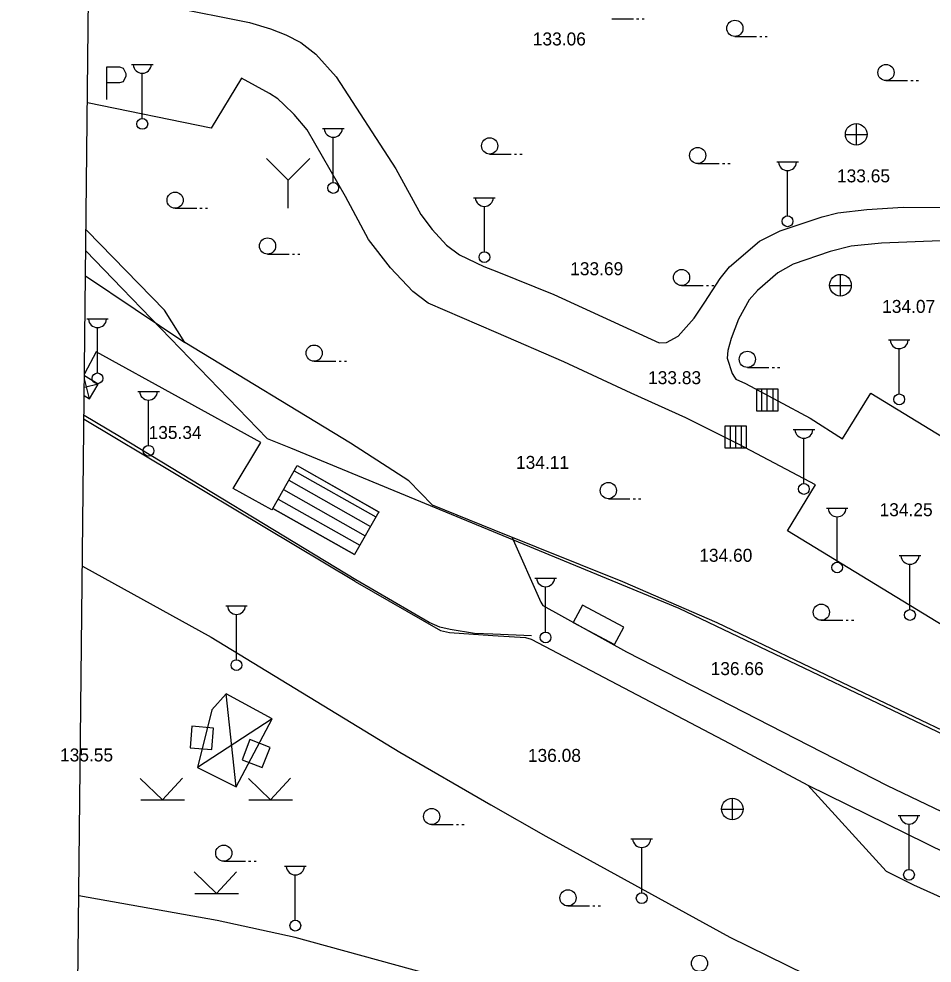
# Model space of a CAD drawing. Extents: x 419101 to 420177, y 4451541 to 4452254.
# Drawn here: x 419101.3 to 419185.8, y 4452064.5 to 4452151.9 of the extents above; entities that cross this region are included whole.
import ezdxf

# ---------------------------------------------------------------- set-up
doc = ezdxf.new("R2010")
doc.units = 0
for name, color, linetype in [('0_ÖNERİ_LEJAND', 7, 'Continuous'), ('2_KADASTRO', 7, 'Continuous'), ('3_HALİHAZIR', 7, 'Continuous')]:
    doc.layers.add(name, color=color, linetype=linetype)

msp = doc.modelspace()

# ---------------------------------------------------------------- linework, layer by layer
at = {"layer": '0_ÖNERİ_LEJAND'}
msp.add_lwpolyline([(419108.722, 4452245.778), (420173.096, 4452234.536), (420165.768, 4451540.511), (419101.295, 4451551.753)], close=True, dxfattribs=at)
at = {"layer": '2_KADASTRO'}
msp.add_lwpolyline([(419107.487, 4452130.446), (419110.859, 4452126.96), (419124.272, 4452113.097), (419126.42, 4452112.21), (419162.35, 4452097.37), (419191.66, 4452083.39), (419209.499, 4452074.263), (419232.354, 4452055.784), (419235.998, 4452053.197), (419252.71, 4452048.61), (419263.65, 4452045.93), (419298.16, 4452038.82), (419313.21, 4452052.63), (419335.67, 4452052.54), (419357.03, 4452053.91), (419363.44, 4452040.24), (419369.82, 4452028.71), (419391.34, 4452027.13), (419408.91, 4452026.12), (419429.01, 4452025.67), (419447.58, 4452025.47), (419467.18, 4452025.82), (419487.11, 4452026.7), (419516.66, 4452028.96)], dxfattribs=at)
at = {"layer": '3_HALİHAZIR'}
for p, q in [((419156.13, 4452151.913), (419158.13, 4452151.913)), ((419158.43, 4452151.913), (419158.63, 4452151.913)), ((419158.93, 4452151.913), (419159.13, 4452151.913)), ((419167.52, 4452150.289), (419169.52, 4452150.289)), ((419169.82, 4452150.289), (419170.02, 4452150.289)), ((419170.32, 4452150.289), (419170.52, 4452150.289)), ((419111.708, 4452147.695), (419113.708, 4452147.695)), ((419112.708, 4452142.695), (419112.708, 4452146.888)), ((419181.496, 4452146.199), (419183.496, 4452146.199)), ((419183.796, 4452146.199), (419183.996, 4452146.199)), ((419184.296, 4452146.199), (419184.496, 4452146.199)), ((419129.372, 4452141.768), (419131.372, 4452141.768)), ((419178.76, 4452140.22), (419178.76, 4452142.22)), ((419130.372, 4452136.768), (419130.372, 4452140.961)), ((419177.739, 4452141.21), (419179.74, 4452141.21)), ((419144.834, 4452139.407), (419146.834, 4452139.407)), ((419147.134, 4452139.407), (419147.334, 4452139.407)), ((419147.634, 4452139.407), (419147.834, 4452139.407)), ((419126.187, 4452137), (419124.187, 4452139)), ((419126.187, 4452137), (419128.197, 4452139)), ((419164.078, 4452138.523), (419166.078, 4452138.523)), ((419166.378, 4452138.523), (419166.578, 4452138.523)), ((419166.878, 4452138.523), (419167.078, 4452138.523)), ((419171.389, 4452138.684), (419173.389, 4452138.684)), ((419172.389, 4452133.684), (419172.389, 4452137.877)), ((419126.187, 4452134.41), (419126.187, 4452137)), ((419143.352, 4452135.368), (419145.352, 4452135.368)), ((419115.745, 4452134.389), (419117.745, 4452134.389)), ((419118.045, 4452134.389), (419118.245, 4452134.389)), ((419118.545, 4452134.389), (419118.745, 4452134.389)), ((419144.352, 4452130.368), (419144.352, 4452134.561)), ((419124.293, 4452130.148), (419126.293, 4452130.148)), ((419126.593, 4452130.148), (419126.793, 4452130.148)), ((419127.093, 4452130.148), (419127.293, 4452130.148)), ((419177.299, 4452126.259), (419177.299, 4452128.259)), ((419162.586, 4452127.233), (419164.586, 4452127.233)), ((419164.886, 4452127.233), (419165.086, 4452127.233)), ((419165.386, 4452127.233), (419165.586, 4452127.233)), ((419176.279, 4452127.249), (419178.279, 4452127.249)), ((419107.566, 4452124.151), (419109.566, 4452124.151)), ((419108.566, 4452119.151), (419108.566, 4452123.344)), ((419181.716, 4452122.204), (419183.716, 4452122.204)), ((419182.716, 4452117.204), (419182.716, 4452121.397)), ((419128.605, 4452120.234), (419130.605, 4452120.234)), ((419130.905, 4452120.234), (419131.105, 4452120.234)), ((419131.405, 4452120.234), (419131.605, 4452120.234)), ((419168.674, 4452119.661), (419170.674, 4452119.661)), ((419170.974, 4452119.661), (419171.174, 4452119.661)), ((419171.474, 4452119.661), (419171.674, 4452119.661)), ((419107.815, 4452116.77), (419107.361, 4452118.599)), ((419108.625, 4452118.111), (419107.352, 4452117.798)), ((419112.287, 4452117.448), (419114.287, 4452117.448)), ((419171.513, 4452117.648), (419169.513, 4452117.648)), ((419169.513, 4452117.648), (419169.513, 4452115.648)), ((419171.513, 4452117.648), (419169.513, 4452117.648)), ((419169.513, 4452117.648), (419169.513, 4452115.648)), ((419170.018, 4452115.648), (419170.018, 4452117.648)), ((419170.513, 4452115.648), (419170.513, 4452117.648)), ((419171.061, 4452115.648), (419171.061, 4452117.648)), ((419171.513, 4452115.648), (419171.513, 4452117.648)), ((419171.513, 4452115.648), (419171.513, 4452117.648)), ((419113.287, 4452112.448), (419113.287, 4452116.641)), ((419169.513, 4452115.648), (419171.513, 4452115.648)), ((419169.513, 4452115.648), (419171.513, 4452115.648)), ((419168.598, 4452114.225), (419166.598, 4452114.225)), ((419166.598, 4452114.225), (419166.598, 4452112.225)), ((419168.598, 4452114.225), (419166.598, 4452114.225)), ((419166.598, 4452114.225), (419166.598, 4452112.225)), ((419167.103, 4452112.225), (419167.103, 4452114.225)), ((419167.598, 4452112.225), (419167.598, 4452114.225)), ((419168.146, 4452112.225), (419168.146, 4452114.225)), ((419168.598, 4452112.225), (419168.598, 4452114.225)), ((419168.598, 4452112.225), (419168.598, 4452114.225)), ((419172.902, 4452113.914), (419174.902, 4452113.914)), ((419173.902, 4452108.914), (419173.902, 4452113.107)), ((419166.598, 4452112.225), (419168.598, 4452112.225)), ((419166.598, 4452112.225), (419168.598, 4452112.225)), ((419126.761, 4452110.096), (419134.32, 4452105.823)), ((419126.268, 4452109.226), (419133.828, 4452104.953)), ((419125.776, 4452108.355), (419133.336, 4452104.082)), ((419125.284, 4452107.484), (419132.844, 4452103.212)), ((419155.818, 4452107.514), (419157.818, 4452107.514)), ((419158.118, 4452107.514), (419158.318, 4452107.514)), ((419158.618, 4452107.514), (419158.818, 4452107.514)), ((419124.792, 4452106.614), (419132.352, 4452102.341)), ((419175.979, 4452106.648), (419177.979, 4452106.648)), ((419176.979, 4452101.648), (419176.979, 4452105.841)), ((419182.714, 4452102.253), (419184.714, 4452102.253)), ((419183.714, 4452097.253), (419183.714, 4452101.446)), ((419149.009, 4452100.172), (419151.009, 4452100.172)), ((419150.009, 4452095.172), (419150.009, 4452099.365)), ((419120.421, 4452097.614), (419122.421, 4452097.614)), ((419121.421, 4452092.614), (419121.421, 4452096.807)), ((419175.512, 4452096.259), (419177.512, 4452096.259)), ((419177.812, 4452096.259), (419178.012, 4452096.259)), ((419178.312, 4452096.259), (419178.512, 4452096.259)), ((419121.403, 4452080.846), (419120.474, 4452089.444)), ((419124.732, 4452087.146), (419117.811, 4452082.637)), ((419114.582, 4452079.647), (419112.522, 4452081.637)), ((419114.582, 4452079.647), (419116.432, 4452081.657)), ((419124.582, 4452079.647), (419122.522, 4452081.637)), ((419124.582, 4452079.647), (419126.432, 4452081.657)), ((419167.297, 4452077.791), (419167.297, 4452079.792)), ((419112.562, 4452079.647), (419116.602, 4452079.647)), ((419122.562, 4452079.647), (419126.602, 4452079.647)), ((419166.277, 4452078.781), (419168.277, 4452078.781)), ((419182.625, 4452078.214), (419184.625, 4452078.214)), ((419139.471, 4452077.357), (419141.471, 4452077.357)), ((419141.771, 4452077.357), (419141.971, 4452077.357)), ((419142.271, 4452077.357), (419142.471, 4452077.357)), ((419183.625, 4452073.214), (419183.625, 4452077.407)), ((419157.9, 4452076.045), (419159.9, 4452076.045)), ((419158.9, 4452071.045), (419158.9, 4452075.238)), ((419120.246, 4452073.965), (419122.246, 4452073.965)), ((419122.546, 4452073.965), (419122.746, 4452073.965)), ((419123.046, 4452073.965), (419123.246, 4452073.965)), ((419119.582, 4452070.987), (419117.522, 4452072.977)), ((419119.582, 4452070.987), (419121.432, 4452072.997)), ((419125.864, 4452073.507), (419127.864, 4452073.507)), ((419126.864, 4452068.507), (419126.864, 4452072.7)), ((419117.562, 4452070.987), (419121.602, 4452070.987)), ((419152.08, 4452069.827), (419154.08, 4452069.827)), ((419154.38, 4452069.827), (419154.58, 4452069.827)), ((419154.88, 4452069.827), (419155.08, 4452069.827))]:
    msp.add_line(p, q, dxfattribs=at)
for points in [[(419107.794, 4452159.109), (419116.402, 4452157.141), (419115.182, 4452153.067), (419122.612, 4452151.583)], [(419122.612, 4452151.583), (419124.577, 4452150.979), (419125.971, 4452150.434), (419127.378, 4452149.717), (419128.755, 4452148.639), (419130.633, 4452146.551), (419136.15, 4452138.048)], [(419109.427, 4452147.467), (419110.597, 4452147.467)], [(419109.427, 4452144.466), (419109.427, 4452147.467)], [(419110.597, 4452147.467), (419110.947, 4452147.347), (419111.187, 4452146.857), (419111.187, 4452146.597), (419110.947, 4452146.087), (419110.597, 4452145.987)], [(419121.872, 4452146.425), (419119.07, 4452141.798), (419107.634, 4452144.134)], [(419131.499, 4452135.47), (419127.96, 4452141.638), (419126.766, 4452143.053), (419125.805, 4452144.002), (419125.249, 4452144.517), (419124.483, 4452145.021), (419121.872, 4452146.425)], [(419110.597, 4452145.987), (419109.427, 4452145.987)], [(419160.524, 4452121.925), (419161.179, 4452121.972), (419162.278, 4452122.567), (419163.767, 4452124.208), (419164.734, 4452125.686), (419166.171, 4452127.892), (419167.036, 4452128.968), (419169.786, 4452131.334), (419171.707, 4452132.309), (419175.598, 4452133.581), (419177.029, 4452133.963), (419179.72, 4452134.26), (419183.085, 4452134.49), (419187.997, 4452134.445), (419188.338, 4452134.525), (419188.692, 4452135.099), (419188.821, 4452135.658), (419188.897, 4452139.871)], [(419136.15, 4452138.048), (419138.487, 4452133.805), (419139.508, 4452132.421), (419140.843, 4452130.981), (419142.035, 4452130.087), (419144.305, 4452129.001), (419145.488, 4452128.526)], [(419145.427, 4452122.9), (419139.153, 4452125.609), (419137.719, 4452126.691), (419135.662, 4452128.873), (419133.64, 4452131.505), (419131.499, 4452135.47)], [(419139.517, 4452106.934), (419137.376, 4452109.16), (419131.955, 4452112.666), (419116.659, 4452121.959), (419114.769, 4452124.971), (419107.598, 4452132.308), (419107.508, 4452132.403)], [(419186.543, 4452131.36), (419181.09, 4452131.151), (419178.269, 4452130.881), (419176.342, 4452130.403), (419172.91, 4452129.207), (419171.492, 4452128.42), (419169.622, 4452126.77), (419168.854, 4452125.917), (419167.858, 4452124.127), (419167.177, 4452122.326), (419166.875, 4452121.233), (419166.81, 4452120.515), (419167.278, 4452119.095)], [(419107.463, 4452128.138), (419116.659, 4452121.959)], [(419145.488, 4452128.526), (419150.772, 4452126.405), (419160.524, 4452121.925)], [(419174.968, 4452108.792), (419167.928, 4452112.53), (419162.971, 4452114.985), (419157.92, 4452117.286), (419151.713, 4452120.186), (419145.427, 4452122.9)], [(419124.791, 4452106.611), (419124.687, 4452106.494), (419121.12, 4452108.447), (419123.66, 4452112.707), (419108.429, 4452121.116), (419107.366, 4452119.064)], [(419167.278, 4452119.095), (419167.471, 4452118.751), (419167.602, 4452118.589), (419168.492, 4452118.178), (419174.468, 4452114.967), (419177.479, 4452113.038)], [(419107.344, 4452117.055), (419107.815, 4452116.77), (419108.625, 4452118.111), (419107.364, 4452118.872)], [(419177.479, 4452113.038), (419180.081, 4452117.281), (419212.288, 4452097.642), (419209.549, 4452093.313)], [(419132.413, 4452099.864), (419107.32, 4452114.84)], [(419132.463, 4452100.02), (419110.602, 4452113.265), (419107.325, 4452115.227)], [(419132.364, 4452102.331), (419124.791, 4452106.611), (419127.029, 4452110.572), (419134.619, 4452106.282)], [(419207.082, 4452089.044), (419204.397, 4452085.029), (419172.389, 4452104.548), (419174.968, 4452108.792)], [(419139.517, 4452106.934), (419145.232, 4452104.639)], [(419145.232, 4452104.639), (419157.129, 4452099.861), (419165.865, 4452096.045), (419178.085, 4452090.199), (419193.366, 4452082.919), (419204.101, 4452077.543), (419211.407, 4452073.615), (419219.737, 4452069.268), (419223.849, 4452066.462), (419233.207, 4452057.383), (419237.681, 4452053.74), (419238.321, 4452053.315), (419247.816, 4452050.428), (419258.408, 4452047.138), (419271.29, 4452044.514), (419281.671, 4452042.479), (419298.463, 4452039.206), (419303.191, 4452040.956), (419304.838, 4452044.42), (419306.698, 4452047.385), (419308.397, 4452049.6), (419309.793, 4452050.452)], [(419146.898, 4452103.97), (419149.562, 4452097.926), (419149.756, 4452097.627), (419157.491, 4452093.356), (419181.607, 4452080.962), (419208.924, 4452067.882), (419237.681, 4452053.74)], [(419107.175, 4452101.286), (419119.093, 4452094.701), (419136.521, 4452084.067)], [(419132.413, 4452099.864), (419140.296, 4452095.319), (419141.123, 4452095.135), (419145.128, 4452094.867)], [(419145.129, 4452094.971), (419143.439, 4452095.039), (419141.176, 4452095.403), (419140.214, 4452095.614), (419139.236, 4452096.05), (419132.463, 4452100.02)], [(419145.128, 4452094.867), (419148.155, 4452094.664), (419148.668, 4452094.513), (419167.05, 4452084.846), (419174.278, 4452081.019), (419181.501, 4452073.033), (419184.031, 4452071.783), (419200.807, 4452064.213), (419219.52, 4452056.671), (419238.815, 4452049.785), (419253.384, 4452045.297), (419263.613, 4452042.521), (419273.695, 4452040.132), (419291.568, 4452036.282), (419298.692, 4452035.133)], [(419148.699, 4452094.827), (419145.129, 4452094.971)], [(419136.521, 4452084.067), (419144.96, 4452079.199)], [(419174.278, 4452081.019), (419196.144, 4452070.227), (419226.898, 4452055.375), (419228.968, 4452053.299)], [(419144.96, 4452079.199), (419150.025, 4452076.278), (419167.053, 4452066.937), (419186.188, 4452057.548), (419204.529, 4452049.256), (419219.751, 4452043.171), (419230.708, 4452039.119), (419243.646, 4452034.898), (419255.592, 4452031.025), (419265.389, 4452028.204), (419274.566, 4452025.842), (419284.15, 4452023.555), (419293.212, 4452021.478), (419302.121, 4452019.581), (419312.246, 4452017.804), (419329.797, 4452015.109), (419344.715, 4452013.146), (419357.367, 4452011.835), (419367.551, 4452010.848)], [(419139.083, 4452063.562), (419126.845, 4452066.924), (419119.648, 4452068.494), (419107.716, 4452070.626), (419106.849, 4452070.761)]]:
    msp.add_lwpolyline(points, dxfattribs=at)
for points in [[(419132.35, 4452102.339), (419124.791, 4452106.611), (419127.029, 4452110.572), (419134.589, 4452106.299)], [(419152.553, 4452096.044), (419156.385, 4452094.015), (419157.245, 4452095.64), (419153.413, 4452097.669)], [(419121.403, 4452080.846), (419124.732, 4452087.146), (419120.474, 4452089.444), (419119.143, 4452087.99), (419117.811, 4452082.637)], [(419117.297, 4452086.451), (419117.136, 4452084.458), (419119.13, 4452084.297), (419119.291, 4452086.29)], [(419122.658, 4452085.22), (419121.943, 4452083.352), (419123.811, 4452082.638), (419124.526, 4452084.506)]]:
    msp.add_lwpolyline(points, close=True, dxfattribs=at)
for centre, radius in [((419167.52, 4452151.039), 0.75), ((419181.496, 4452146.949), 0.75), ((419112.708, 4452142.195), 0.5), ((419178.744, 4452141.228), 1), ((419144.834, 4452140.157), 0.75), ((419164.078, 4452139.273), 0.75), ((419130.372, 4452136.268), 0.5), ((419115.745, 4452135.139), 0.75), ((419172.389, 4452133.184), 0.5), ((419124.293, 4452130.898), 0.75), ((419144.352, 4452129.868), 0.5), ((419162.586, 4452127.983), 0.75), ((419177.284, 4452127.267), 1), ((419128.605, 4452120.984), 0.75), ((419168.674, 4452120.411), 0.75), ((419108.566, 4452118.651), 0.5), ((419182.716, 4452116.704), 0.5), ((419113.287, 4452111.948), 0.5), ((419155.818, 4452108.264), 0.75), ((419173.902, 4452108.414), 0.5), ((419176.979, 4452101.148), 0.5), ((419175.512, 4452097.009), 0.75), ((419183.714, 4452096.753), 0.5), ((419150.009, 4452094.672), 0.5), ((419121.421, 4452092.114), 0.5), ((419167.281, 4452078.8), 1), ((419139.471, 4452078.107), 0.75), ((419120.246, 4452074.715), 0.75), ((419183.625, 4452072.714), 0.5), ((419152.08, 4452070.577), 0.75), ((419158.9, 4452070.545), 0.5), ((419126.864, 4452068.007), 0.5), ((419164.247, 4452064.521), 0.75)]:
    msp.add_circle(centre, radius, dxfattribs=at)
for centre in [(419112.708, 4452147.725), (419130.372, 4452141.797), (419172.389, 4452138.714), (419144.352, 4452135.398), (419108.566, 4452124.181), (419182.716, 4452122.234), (419113.287, 4452117.478), (419173.902, 4452113.944), (419176.979, 4452106.677), (419183.714, 4452102.283), (419150.009, 4452100.202), (419121.421, 4452097.644), (419183.625, 4452078.244), (419158.9, 4452076.075), (419126.864, 4452073.537)]:
    msp.add_arc(centre, 0.837, 183.298, 356.90719, dxfattribs=at)

# ---------------------------------------------------------------- texts
for s, rotation, p in [('133.06 ', 359.99801, (419148.828, 4452149.456)), ('133.65 ', 359.99801, (419176.963, 4452136.787)), ('133.69 ', 359.99801, (419152.285, 4452128.196)), ('134.07 ', 359.99801, (419181.141, 4452124.707)), ('133.83 ', 359.99801, (419159.487, 4452118.114)), ('135.34 ', 359.99831, (419113.289, 4452113.042)), ('134.11 ', 359.99801, (419147.273, 4452110.275)), ('134.25 ', 359.99801, (419180.901, 4452105.897)), ('134.60 ', 359.99801, (419164.226, 4452101.677)), ('136.66 ', 359.99801, (419165.278, 4452091.193)), ('135.55 ', 359.99831, (419105.098, 4452083.199)), ('136.08 ', 359.99801, (419148.374, 4452083.16))]:
    msp.add_text(s, height=1.2, rotation=rotation, dxfattribs=at).set_placement(p)

doc.saveas('drawing.dxf')
